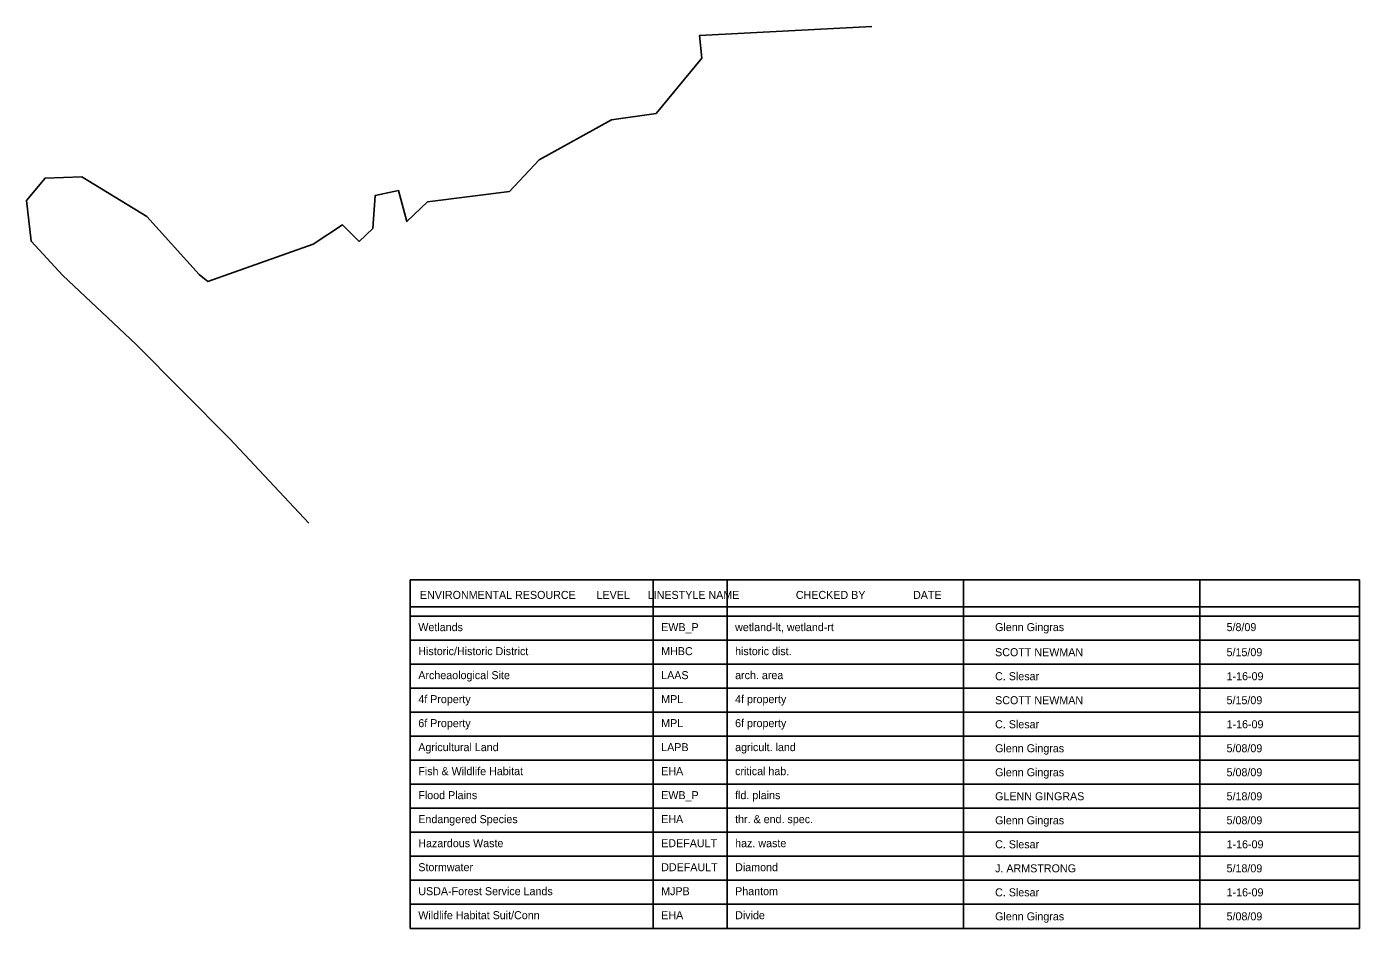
# Model space of a CAD drawing. Extents: x 1509082 to 1511110, y 401167 to 402511.
# Drawn here: x 1510420 to 1511110, y 401233 to 401700 of the extents above; entities that cross this region are included whole.
import ezdxf

# ---------------------------------------------------------------- set-up
doc = ezdxf.new("R2010")
doc.units = 0
doc.layers.add('EWB_P', color=7, linetype='Continuous')
doc.layers.add('NBL1_T', color=7, linetype='Continuous')

msp = doc.modelspace()

# ---------------------------------------------------------------- linework, layer by layer
at = {"layer": 'EWB_P'}
msp.add_lwpolyline([(1510566, 401442.95), (1510525.17, 401486.73), (1510476.49, 401535.75), (1510438.65, 401571.35), (1510422.24, 401589), (1510419.93, 401610.15), (1510429.51, 401621.72), (1510448.53, 401622.45), (1510482.12, 401601.89), (1510509.25, 401571.79), (1510513.71, 401568.13), (1510568.31, 401587.58), (1510583.42, 401597.44), (1510592.11, 401588.94), (1510599.13, 401595.65), (1510600.45, 401612.77), (1510612.46, 401615.28), (1510616.87, 401599.19), (1510627.55, 401609.45), (1510670.04, 401614.82), (1510685.34, 401631.2), (1510722.86, 401651.91), (1510745.89, 401655.26), (1510769.58, 401683.83), (1510768.39, 401695.64), (1510857.67, 401700.17)], dxfattribs=at)
at = {"layer": 'NBL1_T'}
for p, q in [((1510618.62, 401413.71), (1510618.62, 401233.12)), ((1511110.11, 401413.71), (1510618.62, 401413.71)), ((1510744.4, 401413.71), (1510744.4, 401233.12)), ((1510782.69, 401413.71), (1510782.69, 401233.12)), ((1510905.07, 401413.71), (1510905.07, 401233.12)), ((1511027.45, 401233.12), (1511027.44, 401413.71)), ((1511110.11, 401233.12), (1511110.11, 401413.71)), ((1510618.62, 401399.6), (1511110.11, 401399.6)), ((1510618.62, 401394.81), (1511110.11, 401394.83)), ((1510942.63, 401391), (1510942.63, 401391)), ((1510618.62, 401382.37), (1511110.11, 401382.39)), ((1510618.62, 401369.94), (1511110.11, 401369.95)), ((1510618.62, 401357.5), (1511110.11, 401357.52)), ((1510618.62, 401345.06), (1511110.11, 401345.08)), ((1510618.62, 401332.63), (1511110.11, 401332.64)), ((1510618.62, 401320.19), (1511110.11, 401320.21)), ((1510618.62, 401307.75), (1511110.11, 401307.77)), ((1510618.62, 401295.31), (1511110.11, 401295.33)), ((1510618.62, 401282.88), (1511110.11, 401282.9)), ((1510618.62, 401270.44), (1511110.11, 401270.44)), ((1510618.62, 401258), (1511110.11, 401258)), ((1510618.62, 401245.56), (1511110.11, 401245.56)), ((1510618.62, 401233.12), (1511110.11, 401233.12))]:
    msp.add_line(p, q, dxfattribs=at)

# ---------------------------------------------------------------- texts
for s, height, p in [('ENVIRONMENTAL RESOURCE       LEVEL      LINESTYLE NAME                   CHECKED BY                DATE', 4.14556, (1510623.6, 401403.75)), ('Wetlands', 4.146, (1510622.76, 401387.06)), ('wetland-lt, wetland-rt', 4.1456, (1510786.83, 401387.06)), ('Glenn Gingras         ', 4.145, (1510921.48, 401387.08)), ('5/8/09        ', 4.1456, (1511041.35, 401387.07)), ('EWB_P', 4.146, (1510748.54, 401387.06)), ('Historic/Historic District', 4.1456, (1510622.76, 401374.63)), ('MHBC', 4.146, (1510748.54, 401374.63)), ('historic dist.', 4.1456, (1510786.83, 401374.63)), ('SCOTT NEWMAN          ', 4.1456, (1510921.48, 401374.08)), ('5/15/09       ', 4.1456, (1511041.35, 401374.08)), ('Archeaological Site', 4.1456, (1510622.76, 401362.19)), ('LAAS', 4.146, (1510748.54, 401362.19)), ('arch. area', 4.146, (1510786.83, 401362.19)), ('C. Slesar             ', 4.1456, (1510921.48, 401361.64)), ('1-16-09       ', 4.1456, (1511041.35, 401361.64)), ('4f Property', 4.1456, (1510622.76, 401349.76)), ('MPL', 4.146, (1510748.54, 401349.76)), ('4f property', 4.1456, (1510786.83, 401349.76)), ('SCOTT NEWMAN          ', 4.1456, (1510921.48, 401349.21)), ('5/15/09       ', 4.1456, (1511041.35, 401349.21)), ('6f Property', 4.1456, (1510622.76, 401337.33)), ('MPL', 4.146, (1510748.54, 401337.33)), ('6f property', 4.1456, (1510786.83, 401337.33)), ('C. Slesar             ', 4.1456, (1510921.48, 401336.77)), ('1-16-09       ', 4.1456, (1511041.35, 401336.77)), ('Agricultural Land', 4.1456, (1510622.76, 401324.9)), ('agricult. land', 4.1456, (1510786.83, 401324.9)), ('LAPB', 4.146, (1510748.54, 401324.9)), ('Glenn Gingras         ', 4.1456, (1510921.48, 401324.33)), ('5/08/09       ', 4.1456, (1511041.35, 401324.33)), ('Fish & Wildlife Habitat', 4.1456, (1510622.76, 401312.46)), ('EHA', 4.146, (1510748.54, 401312.46)), ('critical hab.', 4.1456, (1510786.83, 401312.46)), ('Glenn Gingras         ', 4.1456, (1510921.48, 401311.9)), ('5/08/09       ', 4.1456, (1511041.35, 401311.9)), ('Flood Plains', 4.1456, (1510622.76, 401300.03)), ('EWB_P', 4.146, (1510748.54, 401300.03)), ('fld. plains', 4.1456, (1510786.83, 401300.03)), ('GLENN GINGRAS         ', 4.1456, (1510921.48, 401299.46)), ('5/18/09       ', 4.1456, (1511041.35, 401299.46)), ('Endangered Species', 4.1456, (1510622.76, 401287.6)), ('EHA', 4.146, (1510748.54, 401287.6)), ('thr. & end. spec.', 4.1456, (1510786.83, 401287.6)), ('Glenn Gingras         ', 4.1456, (1510921.48, 401287.02)), ('5/08/09       ', 4.1456, (1511041.35, 401287.02)), ('Hazardous Waste', 4.1456, (1510622.76, 401275.16)), ('EDEFAULT', 4.146, (1510748.54, 401275.16)), ('haz. waste', 4.146, (1510786.83, 401275.16)), ('C. Slesar             ', 4.1456, (1510921.48, 401274.59)), ('1-16-09       ', 4.1456, (1511041.35, 401274.59)), ('Diamond', 4.146, (1510786.83, 401262.73)), ('Stormwater', 4.146, (1510622.76, 401262.73)), ('DDEFAULT', 4.146, (1510748.54, 401262.73)), ('J. ARMSTRONG          ', 4.1456, (1510921.48, 401262.14)), ('5/18/09       ', 4.1456, (1511041.35, 401262.14)), ('USDA-Forest Service Lands', 4.1456, (1510622.76, 401250.3)), ('MJPB', 4.146, (1510748.54, 401250.3)), ('Phantom', 4.146, (1510786.83, 401250.3)), ('C. Slesar             ', 4.1456, (1510921.48, 401249.7)), ('1-16-09       ', 4.1456, (1511041.35, 401249.7)), ('Wildlife Habitat Suit/Conn', 4.1456, (1510622.76, 401237.86)), ('EHA', 4.146, (1510748.54, 401237.86)), ('Divide', 4.146, (1510786.83, 401237.86)), ('Glenn Gingras         ', 4.1456, (1510921.48, 401237.26)), ('5/08/09       ', 4.1456, (1511041.35, 401237.26))]:
    msp.add_text(s, height=height, dxfattribs=at).set_placement(p)

doc.saveas('drawing.dxf')
